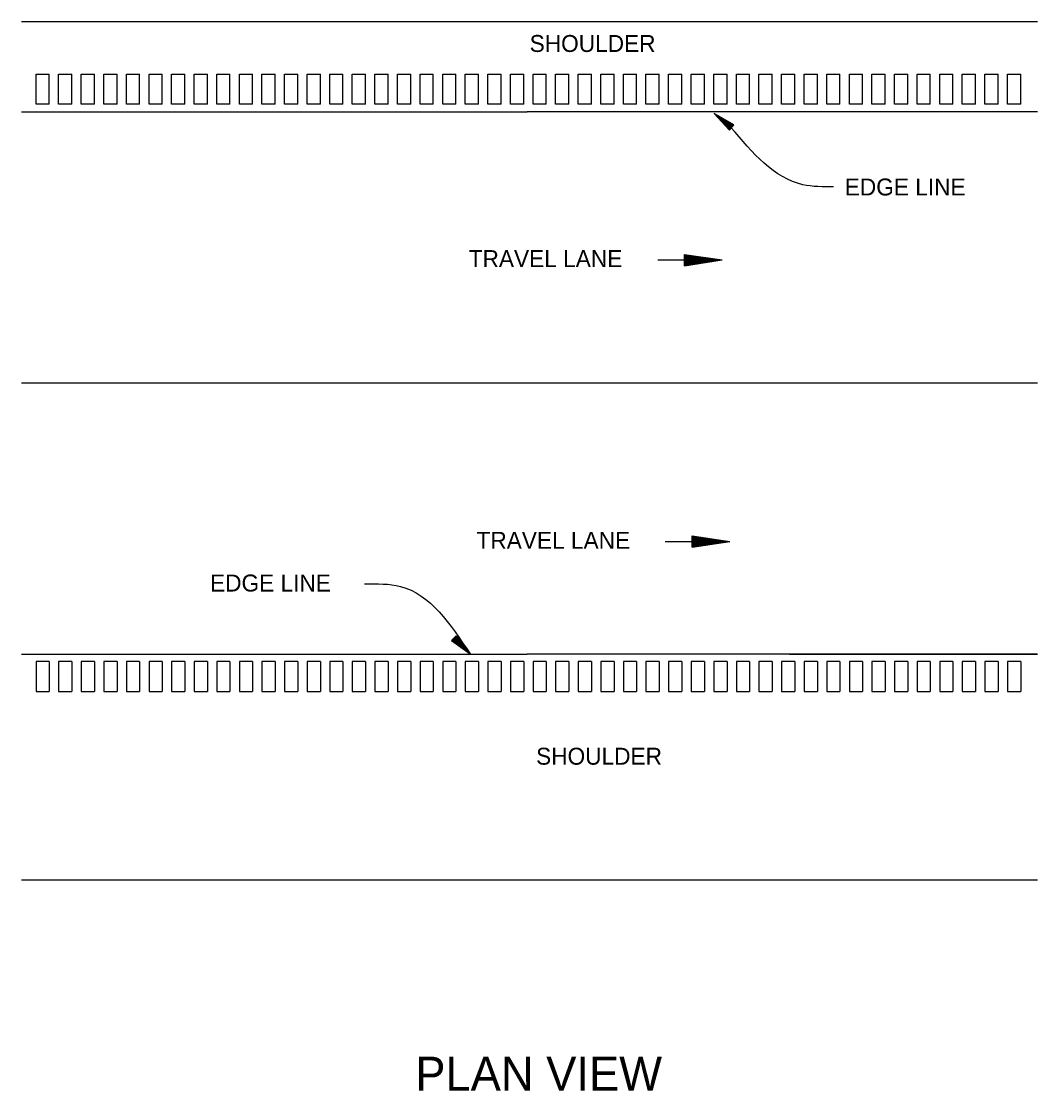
# Model space of a CAD drawing. Extents: x 1929624 to 1935547, y 596315 to 605721.
# Drawn here: x 1932891.9 to 1933161.8, y 600607.3 to 600891.2 of the extents above; entities that cross this region are included whole.
import ezdxf

# ---------------------------------------------------------------- set-up
doc = ezdxf.new("R2010")
doc.units = 0
doc.layers.add('Default', color=7, linetype='Continuous')

msp = doc.modelspace()

# ---------------------------------------------------------------- linework, layer by layer
at = {"layer": 'Default'}
for p, q in [((1932891.85, 600891.24), (1933161.77, 600891.24)), ((1932895.75, 600869.23), (1932895.75, 600877.21)), ((1932895.75, 600877.21), (1932899.26, 600877.21)), ((1932899.26, 600869.23), (1932899.26, 600877.21)), ((1932901.75, 600869.23), (1932901.75, 600877.21)), ((1932901.75, 600877.21), (1932905.26, 600877.21)), ((1932905.26, 600869.23), (1932905.26, 600877.21)), ((1932907.75, 600869.23), (1932907.75, 600877.21)), ((1932907.75, 600877.21), (1932911.26, 600877.21)), ((1932911.26, 600869.23), (1932911.26, 600877.21)), ((1932913.75, 600869.23), (1932913.75, 600877.21)), ((1932913.75, 600877.21), (1932917.26, 600877.21)), ((1932917.26, 600869.23), (1932917.26, 600877.21)), ((1932919.75, 600869.23), (1932919.75, 600877.21)), ((1932919.75, 600877.21), (1932923.26, 600877.21)), ((1932923.26, 600869.23), (1932923.26, 600877.21)), ((1932925.75, 600869.23), (1932925.75, 600877.21)), ((1932925.75, 600877.21), (1932929.26, 600877.21)), ((1932929.26, 600869.23), (1932929.26, 600877.21)), ((1932931.75, 600869.23), (1932931.75, 600877.21)), ((1932931.75, 600877.21), (1932935.26, 600877.21)), ((1932935.26, 600869.23), (1932935.26, 600877.21)), ((1932937.75, 600869.23), (1932937.75, 600877.21)), ((1932937.75, 600877.21), (1932941.26, 600877.21)), ((1932941.26, 600869.23), (1932941.26, 600877.21)), ((1932943.75, 600869.23), (1932943.75, 600877.21)), ((1932943.75, 600877.21), (1932947.26, 600877.21)), ((1932947.26, 600869.23), (1932947.26, 600877.21)), ((1932949.75, 600869.23), (1932949.75, 600877.21)), ((1932949.75, 600877.21), (1932953.26, 600877.21)), ((1932953.26, 600869.23), (1932953.26, 600877.21)), ((1932955.75, 600869.23), (1932955.75, 600877.21)), ((1932955.75, 600877.21), (1932959.26, 600877.21)), ((1932959.26, 600869.23), (1932959.26, 600877.21)), ((1932961.75, 600869.23), (1932961.75, 600877.21)), ((1932961.75, 600877.21), (1932965.26, 600877.21)), ((1932965.26, 600869.23), (1932965.26, 600877.21)), ((1932967.75, 600869.23), (1932967.75, 600877.21)), ((1932967.75, 600877.21), (1932971.26, 600877.21)), ((1932971.26, 600869.23), (1932971.26, 600877.21)), ((1932973.75, 600869.23), (1932973.75, 600877.21)), ((1932973.75, 600877.21), (1932977.26, 600877.21)), ((1932977.26, 600869.23), (1932977.26, 600877.21)), ((1932979.75, 600869.23), (1932979.75, 600877.21)), ((1932979.75, 600877.21), (1932983.26, 600877.21)), ((1932983.26, 600869.23), (1932983.26, 600877.21)), ((1932985.75, 600869.23), (1932985.75, 600877.21)), ((1932985.75, 600869.23), (1932985.75, 600877.21)), ((1932985.75, 600877.21), (1932989.26, 600877.21)), ((1932989.26, 600869.23), (1932989.26, 600877.21)), ((1932991.75, 600869.23), (1932991.75, 600877.21)), ((1932991.75, 600877.21), (1932995.26, 600877.21)), ((1932995.26, 600869.23), (1932995.26, 600877.21)), ((1932997.75, 600869.23), (1932997.75, 600877.21)), ((1932997.75, 600877.21), (1933001.26, 600877.21)), ((1933001.26, 600869.23), (1933001.26, 600877.21)), ((1933003.75, 600869.23), (1933003.75, 600877.21)), ((1933003.75, 600877.21), (1933007.26, 600877.21)), ((1933007.26, 600869.23), (1933007.26, 600877.21)), ((1933009.75, 600869.23), (1933009.75, 600877.21)), ((1933009.75, 600877.21), (1933013.26, 600877.21)), ((1933013.26, 600869.23), (1933013.26, 600877.21)), ((1933015.75, 600869.23), (1933015.75, 600877.21)), ((1933015.75, 600877.21), (1933019.26, 600877.21)), ((1933019.26, 600869.23), (1933019.26, 600877.21)), ((1933021.75, 600869.23), (1933021.75, 600877.21)), ((1933021.75, 600877.21), (1933025.26, 600877.21)), ((1933025.26, 600869.23), (1933025.26, 600877.21)), ((1933027.75, 600869.23), (1933027.75, 600877.21)), ((1933027.75, 600877.21), (1933031.26, 600877.21)), ((1933031.26, 600869.23), (1933031.26, 600877.21)), ((1933033.75, 600869.23), (1933033.75, 600877.21)), ((1933033.75, 600877.21), (1933037.26, 600877.21)), ((1933037.26, 600869.23), (1933037.26, 600877.21)), ((1933039.75, 600869.23), (1933039.75, 600877.21)), ((1933039.75, 600877.21), (1933043.26, 600877.21)), ((1933043.26, 600869.23), (1933043.26, 600877.21)), ((1933045.75, 600869.23), (1933045.75, 600877.21)), ((1933045.75, 600877.21), (1933049.26, 600877.21)), ((1933049.26, 600869.23), (1933049.26, 600877.21)), ((1933051.75, 600869.23), (1933051.75, 600877.21)), ((1933051.75, 600877.21), (1933055.26, 600877.21)), ((1933055.26, 600869.23), (1933055.26, 600877.21)), ((1933057.75, 600869.23), (1933057.75, 600877.21)), ((1933057.75, 600877.21), (1933061.26, 600877.21)), ((1933061.26, 600869.23), (1933061.26, 600877.21)), ((1933063.75, 600869.23), (1933063.75, 600877.21)), ((1933063.75, 600877.21), (1933067.26, 600877.21)), ((1933067.26, 600869.23), (1933067.26, 600877.21)), ((1933069.76, 600869.23), (1933069.76, 600877.21)), ((1933069.76, 600877.21), (1933073.27, 600877.21)), ((1933073.27, 600869.23), (1933073.27, 600877.21)), ((1933075.76, 600869.23), (1933075.76, 600877.21)), ((1933075.76, 600877.21), (1933079.27, 600877.21)), ((1933079.27, 600869.23), (1933079.27, 600877.21)), ((1933081.76, 600869.23), (1933081.76, 600877.21)), ((1933081.76, 600877.21), (1933085.27, 600877.21)), ((1933085.27, 600869.23), (1933085.27, 600877.21)), ((1933087.76, 600869.23), (1933087.76, 600877.21)), ((1933087.76, 600877.21), (1933091.27, 600877.21)), ((1933091.27, 600869.23), (1933091.27, 600877.21)), ((1933093.76, 600869.23), (1933093.76, 600877.21)), ((1933093.76, 600877.21), (1933097.27, 600877.21)), ((1933097.27, 600869.23), (1933097.27, 600877.21)), ((1933099.76, 600869.23), (1933099.76, 600877.21)), ((1933099.76, 600877.21), (1933103.27, 600877.21)), ((1933103.27, 600869.23), (1933103.27, 600877.21)), ((1933105.76, 600869.23), (1933105.76, 600877.21)), ((1933105.76, 600877.21), (1933109.27, 600877.21)), ((1933109.27, 600869.23), (1933109.27, 600877.21)), ((1933111.76, 600869.23), (1933111.76, 600877.21)), ((1933111.76, 600877.21), (1933115.27, 600877.21)), ((1933115.27, 600869.23), (1933115.27, 600877.21)), ((1933117.76, 600869.23), (1933117.76, 600877.21)), ((1933117.76, 600877.21), (1933121.27, 600877.21)), ((1933121.27, 600869.23), (1933121.27, 600877.21)), ((1933123.76, 600869.23), (1933123.76, 600877.21)), ((1933123.76, 600877.21), (1933127.27, 600877.21)), ((1933127.27, 600869.23), (1933127.27, 600877.21)), ((1933129.76, 600869.23), (1933129.76, 600877.21)), ((1933129.76, 600877.21), (1933133.27, 600877.21)), ((1933133.27, 600869.23), (1933133.27, 600877.21)), ((1933135.76, 600869.23), (1933135.76, 600877.21)), ((1933135.76, 600877.21), (1933139.27, 600877.21)), ((1933139.27, 600869.23), (1933139.27, 600877.21)), ((1933141.76, 600869.23), (1933141.76, 600877.21)), ((1933141.76, 600877.21), (1933145.27, 600877.21)), ((1933145.27, 600869.23), (1933145.27, 600877.21)), ((1933147.76, 600869.23), (1933147.76, 600877.21)), ((1933147.76, 600877.21), (1933151.27, 600877.21)), ((1933151.27, 600869.23), (1933151.27, 600877.21)), ((1933153.76, 600869.23), (1933153.76, 600877.21)), ((1933153.76, 600877.21), (1933157.27, 600877.21)), ((1933157.27, 600869.23), (1933157.27, 600877.21)), ((1932899.26, 600869.23), (1932895.75, 600869.23)), ((1932905.26, 600869.23), (1932901.75, 600869.23)), ((1932911.26, 600869.23), (1932907.75, 600869.23)), ((1932917.26, 600869.23), (1932913.75, 600869.23)), ((1932923.26, 600869.23), (1932919.75, 600869.23)), ((1932929.26, 600869.23), (1932925.75, 600869.23)), ((1932935.26, 600869.23), (1932931.75, 600869.23)), ((1932941.26, 600869.23), (1932937.75, 600869.23)), ((1932947.26, 600869.23), (1932943.75, 600869.23)), ((1932953.26, 600869.23), (1932949.75, 600869.23)), ((1932959.26, 600869.23), (1932955.75, 600869.23)), ((1932965.26, 600869.23), (1932961.75, 600869.23)), ((1932971.26, 600869.23), (1932967.75, 600869.23)), ((1932977.26, 600869.23), (1932973.75, 600869.23)), ((1932983.26, 600869.23), (1932979.75, 600869.23)), ((1932989.26, 600869.23), (1932985.75, 600869.23)), ((1932995.26, 600869.23), (1932991.75, 600869.23)), ((1933001.26, 600869.23), (1932997.75, 600869.23)), ((1933007.26, 600869.23), (1933003.75, 600869.23)), ((1933013.26, 600869.23), (1933009.75, 600869.23)), ((1933019.26, 600869.23), (1933015.75, 600869.23)), ((1933025.26, 600869.23), (1933021.75, 600869.23)), ((1933031.26, 600869.23), (1933027.75, 600869.23)), ((1933037.26, 600869.23), (1933033.75, 600869.23)), ((1933043.26, 600869.23), (1933039.75, 600869.23)), ((1933049.26, 600869.23), (1933045.75, 600869.23)), ((1933055.26, 600869.23), (1933051.75, 600869.23)), ((1933061.26, 600869.23), (1933057.75, 600869.23)), ((1933067.26, 600869.23), (1933063.75, 600869.23)), ((1933073.27, 600869.23), (1933069.76, 600869.23)), ((1933079.27, 600869.23), (1933075.76, 600869.23)), ((1933085.27, 600869.23), (1933081.76, 600869.23)), ((1933091.27, 600869.23), (1933087.76, 600869.23)), ((1933097.27, 600869.23), (1933093.76, 600869.23)), ((1933103.27, 600869.23), (1933099.76, 600869.23)), ((1933109.27, 600869.23), (1933105.76, 600869.23)), ((1933115.27, 600869.23), (1933111.76, 600869.23)), ((1933121.27, 600869.23), (1933117.76, 600869.23)), ((1933127.27, 600869.23), (1933123.76, 600869.23)), ((1933133.27, 600869.23), (1933129.76, 600869.23)), ((1933139.27, 600869.23), (1933135.76, 600869.23)), ((1933145.27, 600869.23), (1933141.76, 600869.23)), ((1933151.27, 600869.23), (1933147.76, 600869.23)), ((1933157.27, 600869.23), (1933153.76, 600869.23)), ((1932891.85, 600867.24), (1933026.18, 600867.24)), ((1933161.77, 600867.24), (1933026.18, 600867.24)), ((1933079.97, 600862.32), (1933075.85, 600866.77)), ((1933081.1, 600863.73), (1933075.85, 600866.77)), ((1933080.06, 600862.44), (1933076.63, 600866.14)), ((1933081.01, 600863.61), (1933076.63, 600866.14)), ((1933080.9, 600863.49), (1933077.44, 600865.51)), ((1933080.17, 600862.56), (1933077.44, 600865.51)), ((1933080.26, 600862.68), (1933078.22, 600864.88)), ((1933080.81, 600863.37), (1933078.22, 600864.88)), ((1933080.71, 600863.25), (1933079.01, 600864.24)), ((1933080.35, 600862.8), (1933079.01, 600864.24)), ((1933080.62, 600863.13), (1933079.79, 600863.62)), ((1933080.44, 600862.92), (1933079.79, 600863.62)), ((1933079.97, 600862.32), (1933081.1, 600863.73)), ((1933067.94, 600829.36), (1933078.02, 600827.88)), ((1933067.94, 600826.36), (1933067.94, 600829.36)), ((1933067.94, 600829.12), (1933076.34, 600827.88)), ((1933067.94, 600828.87), (1933074.62, 600827.88)), ((1933067.94, 600828.61), (1933072.95, 600827.88)), ((1933060.86, 600827.88), (1933078.02, 600827.88)), ((1933067.94, 600828.36), (1933071.23, 600827.88)), ((1933067.94, 600828.12), (1933069.55, 600827.88)), ((1933067.94, 600826.36), (1933078.02, 600827.88)), ((1933067.94, 600827.38), (1933071.23, 600827.88)), ((1933067.94, 600826.86), (1933074.62, 600827.88)), ((1933067.94, 600826.6), (1933076.34, 600827.88)), ((1933067.94, 600827.11), (1933072.95, 600827.88)), ((1933067.94, 600827.62), (1933069.55, 600827.88)), ((1932891.85, 600795.24), (1933161.77, 600795.24)), ((1933062.88, 600753.1), (1933080.05, 600753.1)), ((1933069.97, 600754.59), (1933080.05, 600753.1)), ((1933069.97, 600751.59), (1933069.97, 600754.59)), ((1933069.97, 600754.35), (1933078.37, 600753.1)), ((1933069.97, 600754.09), (1933076.64, 600753.1)), ((1933069.97, 600753.84), (1933074.98, 600753.1)), ((1933069.97, 600753.58), (1933073.25, 600753.1)), ((1933069.97, 600753.34), (1933071.57, 600753.1)), ((1933069.97, 600751.59), (1933080.05, 600753.1)), ((1933069.97, 600752.61), (1933073.25, 600753.1)), ((1933069.97, 600752.08), (1933076.64, 600753.1)), ((1933069.97, 600751.83), (1933078.37, 600753.1)), ((1933069.97, 600752.34), (1933074.98, 600753.1)), ((1933069.97, 600752.85), (1933071.57, 600753.1)), ((1933007.35, 600728.11), (1933006.11, 600726.82)), ((1933006.11, 600726.82), (1933011.04, 600723.28)), ((1933006.21, 600726.92), (1933010.32, 600723.98)), ((1933006.32, 600727.03), (1933009.57, 600724.7)), ((1933006.42, 600727.13), (1933008.87, 600725.39)), ((1933006.53, 600727.24), (1933008.13, 600726.1)), ((1933006.63, 600727.36), (1933007.41, 600726.8)), ((1933006.83, 600727.55), (1933007.41, 600726.8)), ((1933006.93, 600727.66), (1933008.13, 600726.1)), ((1933007.04, 600727.78), (1933008.87, 600725.39)), ((1933007.14, 600727.88), (1933009.57, 600724.7)), ((1933007.25, 600727.99), (1933010.32, 600723.98)), ((1933007.35, 600728.11), (1933011.04, 600723.28)), ((1932891.85, 600723.23), (1933026.18, 600723.23)), ((1932899.26, 600721.24), (1932895.75, 600721.24)), ((1932895.75, 600721.24), (1932895.75, 600713.26)), ((1932899.26, 600721.24), (1932899.26, 600713.26)), ((1932905.26, 600721.24), (1932901.75, 600721.24)), ((1932901.75, 600721.24), (1932901.75, 600713.26)), ((1932905.26, 600721.24), (1932905.26, 600713.26)), ((1932911.26, 600721.24), (1932907.75, 600721.24)), ((1932907.75, 600721.24), (1932907.75, 600713.26)), ((1932911.26, 600721.24), (1932911.26, 600713.26)), ((1932917.26, 600721.24), (1932913.75, 600721.24)), ((1932913.75, 600721.24), (1932913.75, 600713.26)), ((1932917.26, 600721.24), (1932917.26, 600713.26)), ((1932923.26, 600721.24), (1932919.75, 600721.24)), ((1932919.75, 600721.24), (1932919.75, 600713.26)), ((1932923.26, 600721.24), (1932923.26, 600713.26)), ((1932929.26, 600721.24), (1932925.75, 600721.24)), ((1932925.75, 600721.24), (1932925.75, 600713.26)), ((1932929.26, 600721.24), (1932929.26, 600713.26)), ((1932935.26, 600721.24), (1932931.75, 600721.24)), ((1932931.75, 600721.24), (1932931.75, 600713.26)), ((1932935.26, 600721.24), (1932935.26, 600713.26)), ((1932941.26, 600721.24), (1932937.75, 600721.24)), ((1932937.75, 600721.24), (1932937.75, 600713.26)), ((1932941.26, 600721.24), (1932941.26, 600713.26)), ((1932947.26, 600721.24), (1932943.75, 600721.24)), ((1932943.75, 600721.24), (1932943.75, 600713.26)), ((1932947.26, 600721.24), (1932947.26, 600713.26)), ((1932953.26, 600721.24), (1932949.75, 600721.24)), ((1932949.75, 600721.24), (1932949.75, 600713.26)), ((1932953.26, 600721.24), (1932953.26, 600713.26)), ((1932959.26, 600721.24), (1932955.75, 600721.24)), ((1932955.75, 600721.24), (1932955.75, 600713.26)), ((1932959.26, 600721.24), (1932959.26, 600713.26)), ((1932965.26, 600721.24), (1932961.75, 600721.24)), ((1932961.75, 600721.24), (1932961.75, 600713.26)), ((1932965.26, 600721.24), (1932965.26, 600713.26)), ((1932971.26, 600721.24), (1932967.75, 600721.24)), ((1932967.75, 600721.24), (1932967.75, 600713.26)), ((1932971.26, 600721.24), (1932971.26, 600713.26)), ((1932977.26, 600721.24), (1932973.75, 600721.24)), ((1932973.75, 600721.24), (1932973.75, 600713.26)), ((1932977.26, 600721.24), (1932977.26, 600713.26)), ((1932983.26, 600721.24), (1932979.75, 600721.24)), ((1932979.75, 600721.24), (1932979.75, 600713.26)), ((1932983.26, 600721.24), (1932983.26, 600713.26)), ((1932989.26, 600721.24), (1932985.75, 600721.24)), ((1932985.75, 600721.24), (1932985.75, 600713.26)), ((1932989.26, 600721.24), (1932989.26, 600713.26)), ((1932995.26, 600721.24), (1932991.75, 600721.24)), ((1932991.75, 600721.24), (1932991.75, 600713.26)), ((1932995.26, 600721.24), (1932995.26, 600713.26)), ((1933001.26, 600721.24), (1932997.75, 600721.24)), ((1932997.75, 600721.24), (1932997.75, 600713.26)), ((1933001.26, 600721.24), (1933001.26, 600713.26)), ((1933007.26, 600721.24), (1933003.75, 600721.24)), ((1933003.75, 600721.24), (1933003.75, 600713.26)), ((1933007.26, 600721.24), (1933007.26, 600713.26)), ((1933013.26, 600721.24), (1933009.75, 600721.24)), ((1933009.75, 600721.24), (1933009.75, 600713.26)), ((1933013.26, 600721.24), (1933013.26, 600713.26)), ((1933019.26, 600721.24), (1933015.75, 600721.24)), ((1933015.75, 600721.24), (1933015.75, 600713.26)), ((1933019.26, 600721.24), (1933019.26, 600713.26)), ((1933025.26, 600721.24), (1933021.75, 600721.24)), ((1933021.75, 600721.24), (1933021.75, 600713.26)), ((1933025.26, 600721.24), (1933025.26, 600713.26)), ((1933161.77, 600723.23), (1933026.18, 600723.23)), ((1933031.26, 600721.24), (1933027.75, 600721.24)), ((1933027.75, 600721.24), (1933027.75, 600713.26)), ((1933031.26, 600721.24), (1933031.26, 600713.26)), ((1933037.26, 600721.24), (1933033.75, 600721.24)), ((1933033.75, 600721.24), (1933033.75, 600713.26)), ((1933037.26, 600721.24), (1933037.26, 600713.26)), ((1933043.26, 600721.24), (1933039.75, 600721.24)), ((1933039.75, 600721.24), (1933039.75, 600713.26)), ((1933043.26, 600721.24), (1933043.26, 600713.26)), ((1933049.26, 600721.24), (1933045.75, 600721.24)), ((1933045.75, 600721.24), (1933045.75, 600713.26)), ((1933049.26, 600721.24), (1933049.26, 600713.26)), ((1933055.26, 600721.24), (1933051.75, 600721.24)), ((1933051.75, 600721.24), (1933051.75, 600713.26)), ((1933055.26, 600721.24), (1933055.26, 600713.26)), ((1933061.26, 600721.24), (1933057.75, 600721.24)), ((1933057.75, 600721.24), (1933057.75, 600713.26)), ((1933061.26, 600721.24), (1933061.26, 600713.26)), ((1933067.26, 600721.24), (1933063.75, 600721.24)), ((1933063.75, 600721.24), (1933063.75, 600713.26)), ((1933067.26, 600721.24), (1933067.26, 600713.26)), ((1933073.27, 600721.24), (1933069.76, 600721.24)), ((1933069.76, 600721.24), (1933069.76, 600713.26)), ((1933073.27, 600721.24), (1933073.27, 600713.26)), ((1933079.27, 600721.24), (1933075.76, 600721.24)), ((1933075.76, 600721.24), (1933075.76, 600713.26)), ((1933079.27, 600721.24), (1933079.27, 600713.26)), ((1933085.27, 600721.24), (1933081.76, 600721.24)), ((1933081.76, 600721.24), (1933081.76, 600713.26)), ((1933085.27, 600721.24), (1933085.27, 600713.26)), ((1933091.27, 600721.24), (1933087.76, 600721.24)), ((1933087.76, 600721.24), (1933087.76, 600713.26)), ((1933091.27, 600721.24), (1933091.27, 600713.26)), ((1933097.27, 600721.24), (1933093.76, 600721.24)), ((1933093.76, 600721.24), (1933093.76, 600713.26)), ((1933095.86, 600723.23), (1933161.77, 600723.23)), ((1933097.27, 600721.24), (1933097.27, 600713.26)), ((1933103.27, 600721.24), (1933099.76, 600721.24)), ((1933099.76, 600721.24), (1933099.76, 600713.26)), ((1933103.27, 600721.24), (1933103.27, 600713.26)), ((1933109.27, 600721.24), (1933105.76, 600721.24)), ((1933105.76, 600721.24), (1933105.76, 600713.26)), ((1933109.27, 600721.24), (1933109.27, 600713.26)), ((1933115.27, 600721.24), (1933111.76, 600721.24)), ((1933111.76, 600721.24), (1933111.76, 600713.26)), ((1933115.27, 600721.24), (1933115.27, 600713.26)), ((1933121.27, 600721.24), (1933117.76, 600721.24)), ((1933117.76, 600721.24), (1933117.76, 600713.26)), ((1933121.27, 600721.24), (1933121.27, 600713.26)), ((1933127.27, 600721.24), (1933123.76, 600721.24)), ((1933123.76, 600721.24), (1933123.76, 600713.26)), ((1933127.27, 600721.24), (1933127.27, 600713.26)), ((1933133.27, 600721.24), (1933129.76, 600721.24)), ((1933129.76, 600721.24), (1933129.76, 600713.26)), ((1933133.27, 600721.24), (1933133.27, 600713.26)), ((1933139.27, 600721.24), (1933135.76, 600721.24)), ((1933135.76, 600721.24), (1933135.76, 600713.26)), ((1933139.27, 600721.24), (1933139.27, 600713.26)), ((1933145.27, 600721.24), (1933141.76, 600721.24)), ((1933141.76, 600721.24), (1933141.76, 600713.26)), ((1933145.27, 600721.24), (1933145.27, 600713.26)), ((1933151.27, 600721.24), (1933147.76, 600721.24)), ((1933147.76, 600721.24), (1933147.76, 600713.26)), ((1933151.27, 600721.24), (1933151.27, 600713.26)), ((1933157.27, 600721.24), (1933153.76, 600721.24)), ((1933153.76, 600721.24), (1933153.76, 600713.26)), ((1933157.27, 600721.24), (1933157.27, 600713.26)), ((1932895.75, 600713.26), (1932899.26, 600713.26)), ((1932901.75, 600713.26), (1932905.26, 600713.26)), ((1932907.75, 600713.26), (1932911.26, 600713.26)), ((1932913.75, 600713.26), (1932917.26, 600713.26)), ((1932919.75, 600713.26), (1932923.26, 600713.26)), ((1932925.75, 600713.26), (1932929.26, 600713.26)), ((1932931.75, 600713.26), (1932935.26, 600713.26)), ((1932937.75, 600713.26), (1932941.26, 600713.26)), ((1932943.75, 600713.26), (1932947.26, 600713.26)), ((1932949.75, 600713.26), (1932953.26, 600713.26)), ((1932955.75, 600713.26), (1932959.26, 600713.26)), ((1932961.75, 600713.26), (1932965.26, 600713.26)), ((1932967.75, 600713.26), (1932971.26, 600713.26)), ((1932973.75, 600713.26), (1932977.26, 600713.26)), ((1932979.75, 600713.26), (1932983.26, 600713.26)), ((1932985.75, 600713.26), (1932989.26, 600713.26)), ((1932991.75, 600713.26), (1932995.26, 600713.26)), ((1932997.75, 600713.26), (1933001.26, 600713.26)), ((1933003.75, 600713.26), (1933007.26, 600713.26)), ((1933009.75, 600713.26), (1933013.26, 600713.26)), ((1933015.75, 600713.26), (1933019.26, 600713.26)), ((1933021.75, 600713.26), (1933025.26, 600713.26)), ((1933027.75, 600713.26), (1933031.26, 600713.26)), ((1933033.75, 600713.26), (1933037.26, 600713.26)), ((1933039.75, 600713.26), (1933043.26, 600713.26)), ((1933045.75, 600713.26), (1933049.26, 600713.26)), ((1933051.75, 600713.26), (1933055.26, 600713.26)), ((1933057.75, 600713.26), (1933061.26, 600713.26)), ((1933063.75, 600713.26), (1933067.26, 600713.26)), ((1933069.76, 600713.26), (1933073.27, 600713.26)), ((1933075.76, 600713.26), (1933079.27, 600713.26)), ((1933081.76, 600713.26), (1933085.27, 600713.26)), ((1933087.76, 600713.26), (1933091.27, 600713.26)), ((1933093.76, 600713.26), (1933097.27, 600713.26)), ((1933099.76, 600713.26), (1933103.27, 600713.26)), ((1933105.76, 600713.26), (1933109.27, 600713.26)), ((1933111.76, 600713.26), (1933115.27, 600713.26)), ((1933117.76, 600713.26), (1933121.27, 600713.26)), ((1933123.76, 600713.26), (1933127.27, 600713.26)), ((1933129.76, 600713.26), (1933133.27, 600713.26)), ((1933135.76, 600713.26), (1933139.27, 600713.26)), ((1933141.76, 600713.26), (1933145.27, 600713.26)), ((1933147.76, 600713.26), (1933151.27, 600713.26)), ((1933153.76, 600713.26), (1933157.27, 600713.26)), ((1932891.85, 600663.23), (1933161.77, 600663.23))]:
    msp.add_line(p, q, dxfattribs=at)
for points in [[(1933107.56, 600847.27), (1933099.43, 600847.86), (1933080.32, 600863.08)], [(1932982.99, 600741.85), (1932992.55, 600741.19), (1933011.04, 600723.28)]]:
    msp.add_spline(points, degree=3, dxfattribs=at)

# ---------------------------------------------------------------- texts
for s, height, p in [('SHOULDER', 4.5, (1933026.85, 600883.12)), ('EDGE LINE', 4.5, (1933110.54, 600845.01)), ('TRAVEL LANE', 4.5001, (1933010.66, 600825.99)), ('TRAVEL LANE', 4.5001, (1933012.74, 600751.18)), ('EDGE LINE', 4.5, (1932941.96, 600739.84)), ('SHOULDER', 4.5, (1933028.56, 600693.85)), ('PLAN VIEW ', 9, (1932996.46, 600607.3))]:
    msp.add_text(s, height=height, dxfattribs=at).set_placement(p)

doc.saveas('drawing.dxf')
